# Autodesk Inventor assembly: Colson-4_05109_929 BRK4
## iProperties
Created: 2010-10
Part Number: Colson-4_05109_929 BRK4
Document SubType Name: Assembly
Designer: Administrator
Translation Standard: STEP AP214IS
FileName: Colson-4.05109.929 BRK4.step.step
PreProcessor: SolidWorks 2011
PostProcessor: Build: 236a, Release: 2009 RTM - Date: Fri 02/22/2008
Sent Units: Inches
Uncertainty: 1e-05
Author: Administrator
